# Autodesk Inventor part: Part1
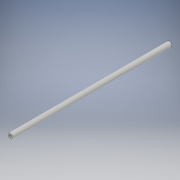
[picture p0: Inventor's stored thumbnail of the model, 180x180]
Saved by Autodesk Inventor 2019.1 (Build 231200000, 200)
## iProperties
Created: 2018-09
Part Number: Part1
Material: Generic
Document SubType Name: Modeling
Designer: drawing
Density: 1 g/cm^3
Appearance: Default
Author: drawing
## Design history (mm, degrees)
sketch "Sketch1"
  geometry: C1 r 3.175 at (0, 0); 1 further point
  constraints: 1 centre point, 1 coincident
  dimensions: "d0" = 6.35 diameter of C1
extrude "Extrusion1" new body sketch "Sketch1" stored distance "d1" = 203.708; taper "d2" = 0 deg
sketch "Sketch2"
  geometry: 2 further points
  constraints: 1 coincident
hole "Hole1" sketch "Sketch2" at (0, 0) diameter "d3" = 3.302; stored, may be unused: countersink angle "d7" = 82 deg, drill point angle "d9" = 118 deg; dims "d4" = 8.3312, "d5" = 7.1374, "d6" = 3.5052, "d8" = 12.2936
mirror "Mirror1"
body "Solid1"
